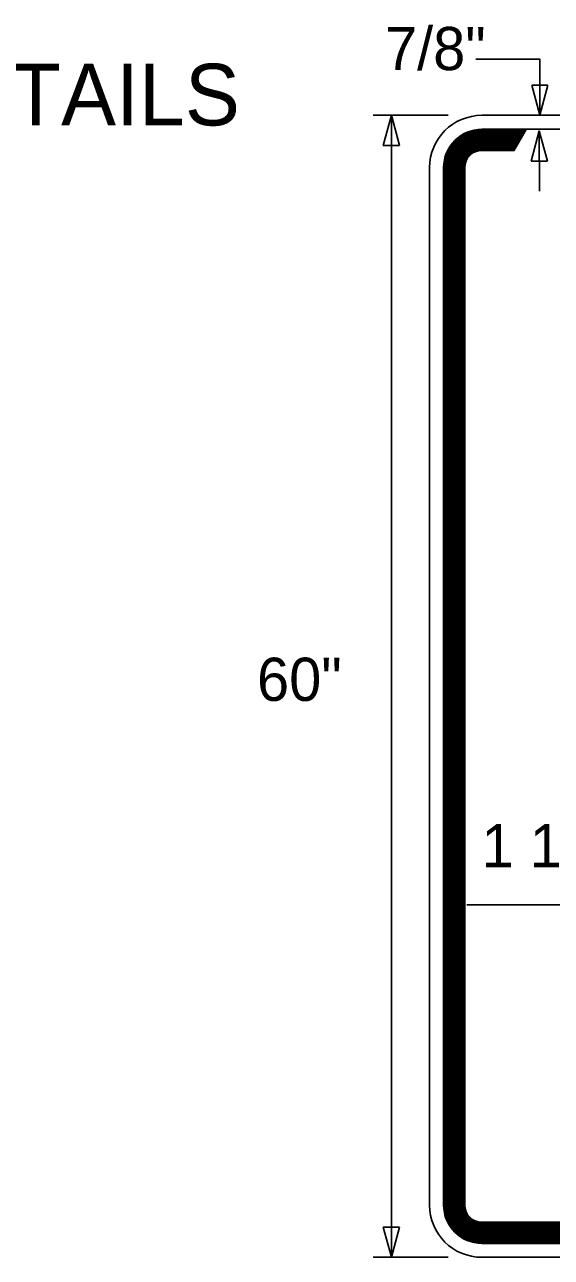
# Model space of a CAD drawing. Extents: x 15278 to 18126, y 1908 to 6555.
# Drawn here: x 17744.9 to 17847.4, y 2366.5 to 2606.5 of the extents above; entities that cross this region are included whole.
import ezdxf

# ---------------------------------------------------------------- set-up
doc = ezdxf.new("R2010")
doc.units = 0
doc.layers.add('TYPICAL_EX', color=7, linetype='Continuous')
doc.layers.add('TYPICAL_TEXT_DIMEN_PR', color=7, linetype='Continuous')

msp = doc.modelspace()

# ---------------------------------------------------------------- linework, layer by layer
at = {"layer": 'TYPICAL_EX'}
for p, q in [((17976.4, 2588.82), (17833.88, 2588.82)), ((17842.58, 2586.1), (17833.89, 2586.1)), ((17842.52, 2585.99), (17833.89, 2585.99)), ((17842.45, 2585.88), (17833.89, 2585.88)), ((17842.39, 2585.77), (17833.89, 2585.77)), ((17842.32, 2585.66), (17833.89, 2585.66)), ((17842.26, 2585.54), (17833.89, 2585.54)), ((17842.19, 2585.43), (17833.89, 2585.43)), ((17842.13, 2585.32), (17833.89, 2585.32)), ((17842.06, 2585.21), (17833.89, 2585.21)), ((17842, 2585.1), (17833.89, 2585.1)), ((17841.94, 2584.98), (17833.89, 2584.98)), ((17841.87, 2584.87), (17833.89, 2584.87)), ((17841.81, 2584.76), (17833.89, 2584.76)), ((17841.74, 2584.65), (17833.89, 2584.65)), ((17841.68, 2584.53), (17833.89, 2584.53)), ((17841.61, 2584.42), (17833.89, 2584.42)), ((17841.55, 2584.31), (17833.89, 2584.31)), ((17841.48, 2584.2), (17833.89, 2584.2)), ((17846.51, 2586.1), (17842.51, 2586.1)), ((17976.4, 2586.1), (17846.51, 2586.1)), ((17841.42, 2584.09), (17833.89, 2584.09)), ((17841.35, 2583.97), (17833.89, 2583.97)), ((17841.29, 2583.86), (17833.89, 2583.86)), ((17841.22, 2583.75), (17833.89, 2583.75)), ((17841.16, 2583.64), (17833.89, 2583.64)), ((17841.1, 2583.53), (17833.89, 2583.53)), ((17841.03, 2583.41), (17833.89, 2583.41)), ((17840.97, 2583.3), (17833.89, 2583.3)), ((17840.9, 2583.19), (17833.89, 2583.19)), ((17840.84, 2583.08), (17833.89, 2583.08)), ((17840.77, 2582.97), (17833.89, 2582.97)), ((17840.71, 2582.85), (17833.89, 2582.85)), ((17840.64, 2582.74), (17833.89, 2582.74)), ((17840.58, 2582.63), (17833.89, 2582.63)), ((17840.51, 2582.52), (17833.89, 2582.52)), ((17840.45, 2582.41), (17833.89, 2582.41)), ((17840.39, 2582.29), (17833.89, 2582.29)), ((17840.32, 2582.18), (17833.89, 2582.18)), ((17840.26, 2582.07), (17833.89, 2582.07)), ((17840.21, 2581.99), (17833.89, 2581.99)), ((17823.7, 2578.64), (17823.7, 2430.55)), ((17826.42, 2578.64), (17826.42, 2430.55)), ((17826.53, 2578.64), (17826.53, 2430.55)), ((17826.64, 2578.64), (17826.64, 2430.55)), ((17826.76, 2578.64), (17826.76, 2430.55)), ((17826.87, 2578.64), (17826.87, 2430.42)), ((17826.98, 2578.64), (17826.98, 2430.55)), ((17827.09, 2578.64), (17827.09, 2430.55)), ((17827.2, 2578.64), (17827.2, 2430.53)), ((17827.32, 2578.64), (17827.32, 2430.56)), ((17827.43, 2578.64), (17827.43, 2430.51)), ((17827.54, 2578.64), (17827.54, 2430.55)), ((17827.65, 2578.64), (17827.65, 2430.55)), ((17827.76, 2578.64), (17827.76, 2430.59)), ((17827.88, 2578.64), (17827.88, 2430.55)), ((17827.99, 2578.64), (17827.99, 2430.55)), ((17828.1, 2578.64), (17828.1, 2430.55)), ((17828.21, 2578.64), (17828.21, 2430.55)), ((17828.33, 2578.64), (17828.33, 2430.55)), ((17828.44, 2578.64), (17828.44, 2430.54)), ((17828.55, 2578.64), (17828.55, 2430.55)), ((17828.66, 2578.64), (17828.66, 2430.56)), ((17828.77, 2578.64), (17828.77, 2430.55)), ((17828.89, 2578.64), (17828.89, 2430.55)), ((17829, 2578.64), (17829, 2430.54)), ((17829.11, 2578.64), (17829.11, 2430.57)), ((17829.22, 2578.64), (17829.22, 2430.55)), ((17829.33, 2578.64), (17829.33, 2430.55)), ((17829.44, 2578.64), (17829.44, 2449.25)), ((17829.56, 2578.64), (17829.56, 2449.25)), ((17829.67, 2578.64), (17829.67, 2449.25)), ((17829.78, 2578.64), (17829.78, 2430.55)), ((17829.89, 2578.64), (17829.89, 2430.54)), ((17830.01, 2578.64), (17830.01, 2430.55)), ((17830.12, 2578.64), (17830.12, 2430.54)), ((17830.23, 2578.64), (17830.23, 2430.55)), ((17830.34, 2578.64), (17830.34, 2430.57)), ((17830.45, 2578.64), (17830.45, 2430.56)), ((17830.53, 2578.64), (17830.53, 2430.57)), ((17829.44, 2449.33), (17829.44, 2376.7)), ((17829.56, 2449.25), (17829.56, 2376.7)), ((17829.67, 2449.25), (17829.67, 2376.7)), ((17830.94, 2435.12), (17979.69, 2435.12)), ((17823.7, 2430.55), (17823.7, 2376.7)), ((17826.42, 2430.55), (17826.42, 2376.7)), ((17826.53, 2430.55), (17826.53, 2376.7)), ((17826.64, 2430.55), (17826.64, 2376.7)), ((17826.76, 2430.55), (17826.76, 2376.7)), ((17826.87, 2430.55), (17826.87, 2376.7)), ((17826.98, 2430.55), (17826.98, 2376.7)), ((17827.09, 2430.55), (17827.09, 2376.7)), ((17827.2, 2430.55), (17827.2, 2376.03)), ((17827.32, 2430.55), (17827.32, 2376.7)), ((17827.43, 2430.55), (17827.43, 2376.7)), ((17827.54, 2430.55), (17827.54, 2376.7)), ((17827.65, 2430.55), (17827.65, 2376.7)), ((17827.76, 2430.6), (17827.76, 2376.7)), ((17827.88, 2430.55), (17827.88, 2376.7)), ((17827.99, 2430.55), (17827.99, 2376.7)), ((17828.1, 2430.55), (17828.1, 2376.7)), ((17828.21, 2430.55), (17828.21, 2376.7)), ((17828.33, 2430.55), (17828.33, 2376.7)), ((17828.44, 2430.55), (17828.44, 2376.7)), ((17828.55, 2430.55), (17828.55, 2376.7)), ((17828.66, 2430.55), (17828.66, 2376.7)), ((17828.77, 2430.55), (17828.77, 2376.7)), ((17828.89, 2430.55), (17828.89, 2376.7)), ((17829, 2430.55), (17829, 2376.7)), ((17829.11, 2430.55), (17829.11, 2376.7)), ((17829.22, 2430.55), (17829.22, 2376.7)), ((17829.33, 2430.55), (17829.33, 2376.7)), ((17829.78, 2430.55), (17829.78, 2376.7)), ((17829.89, 2430.55), (17829.89, 2376.7)), ((17830.01, 2430.55), (17830.01, 2376.7)), ((17830.12, 2430.54), (17830.12, 2376.7)), ((17830.23, 2430.55), (17830.23, 2376.7)), ((17830.34, 2430.55), (17830.34, 2376.7)), ((17830.45, 2430.55), (17830.45, 2376.7)), ((17830.53, 2430.55), (17830.53, 2376.7)), ((17833.88, 2373.35), (17976.4, 2373.35)), ((17833.88, 2373.27), (17976.4, 2373.27)), ((17833.88, 2373.16), (17976.4, 2373.16)), ((17833.88, 2373.05), (17976.4, 2373.05)), ((17833.88, 2372.94), (17976.4, 2372.94)), ((17833.88, 2372.83), (17976.4, 2372.83)), ((17833.88, 2372.71), (17976.4, 2372.71)), ((17833.88, 2372.6), (17976.4, 2372.6)), ((17833.88, 2372.49), (17976.4, 2372.49)), ((17833.88, 2372.38), (17976.4, 2372.38)), ((17833.88, 2372.27), (17976.4, 2372.27)), ((17833.88, 2372.15), (17976.4, 2372.15)), ((17833.88, 2372.04), (17976.4, 2372.04)), ((17833.88, 2371.93), (17976.4, 2371.93)), ((17833.88, 2371.82), (17976.4, 2371.82)), ((17833.88, 2371.7), (17976.4, 2371.7)), ((17833.88, 2371.59), (17976.4, 2371.59)), ((17833.88, 2371.48), (17976.4, 2371.48)), ((17833.88, 2371.37), (17976.4, 2371.37)), ((17833.88, 2371.26), (17976.4, 2371.26)), ((17833.88, 2371.14), (17976.4, 2371.14)), ((17833.88, 2371.03), (17976.4, 2371.03)), ((17833.88, 2370.92), (17976.4, 2370.92)), ((17833.88, 2370.81), (17976.4, 2370.81)), ((17833.88, 2370.7), (17976.4, 2370.7)), ((17833.88, 2370.59), (17976.4, 2370.59)), ((17833.88, 2370.47), (17976.4, 2370.47)), ((17833.88, 2370.36), (17976.4, 2370.36)), ((17833.88, 2370.25), (17976.4, 2370.25)), ((17833.88, 2370.14), (17976.4, 2370.14)), ((17833.88, 2370.02), (17976.4, 2370.02)), ((17833.88, 2369.91), (17976.4, 2369.91)), ((17833.88, 2369.8), (17976.4, 2369.8)), ((17833.88, 2369.69), (17976.4, 2369.69)), ((17833.88, 2369.58), (17976.4, 2369.58)), ((17833.88, 2369.46), (17976.4, 2369.46)), ((17833.88, 2369.35), (17976.4, 2369.35)), ((17833.88, 2369.24), (17976.4, 2369.24)), ((17833.88, 2366.53), (17976.4, 2366.53))]:
    msp.add_line(p, q, dxfattribs=at)
for centre, radius, start, end in [((17833.88, 2578.64), 10.18, 90, 180), ((17833.88, 2578.64), 7.46, 90, 180), ((17833.88, 2578.64), 7.35, 90, 180), ((17833.88, 2578.64), 7.24, 90, 180), ((17833.88, 2578.64), 7.13, 90, 180), ((17833.88, 2578.64), 7.02, 90, 180), ((17833.88, 2578.64), 6.9, 90, 180), ((17833.88, 2578.64), 6.79, 90, 180), ((17833.88, 2578.64), 6.68, 90, 180), ((17833.88, 2578.64), 6.57, 90, 180), ((17833.88, 2578.64), 6.46, 90, 180), ((17833.88, 2578.64), 6.34, 90, 180), ((17833.88, 2578.64), 6.23, 90, 180), ((17833.88, 2578.64), 6.12, 90, 180), ((17833.88, 2578.64), 6.01, 90, 180), ((17833.88, 2578.64), 5.9, 90, 180), ((17833.88, 2578.64), 5.78, 90, 180), ((17833.88, 2578.64), 5.67, 90, 180), ((17833.88, 2578.64), 5.56, 90, 180), ((17833.88, 2578.64), 5.45, 90, 180), ((17833.88, 2578.64), 5.34, 90, 180), ((17833.88, 2578.64), 5.22, 90, 180), ((17833.88, 2578.64), 5.11, 90, 180), ((17833.88, 2578.64), 5, 90, 180), ((17833.88, 2578.64), 4.89, 90, 180), ((17833.88, 2578.64), 4.78, 90, 180), ((17833.88, 2578.64), 4.66, 90, 180), ((17833.88, 2578.64), 4.55, 90, 180), ((17833.88, 2578.64), 4.44, 90, 180), ((17833.88, 2578.64), 4.33, 90, 180), ((17833.88, 2578.64), 4.21, 90, 180), ((17833.88, 2578.64), 4.1, 90, 180), ((17833.88, 2578.64), 3.99, 90, 180), ((17833.88, 2578.64), 3.88, 90, 180), ((17833.88, 2578.64), 3.77, 90, 180), ((17833.88, 2578.64), 3.65, 90, 180), ((17833.88, 2578.64), 3.54, 90, 180), ((17833.88, 2578.64), 3.43, 90, 180), ((17833.88, 2578.64), 3.36, 90, 180), ((17833.88, 2376.71), 10.18, 180, 270), ((17833.88, 2376.71), 7.46, 180, 270), ((17833.88, 2376.71), 7.35, 180, 270), ((17833.88, 2376.71), 7.24, 180, 270), ((17833.88, 2376.71), 7.13, 180, 270), ((17833.88, 2376.71), 7.02, 180, 270), ((17833.88, 2376.71), 6.9, 180, 270), ((17833.88, 2376.71), 6.79, 180, 270), ((17833.88, 2376.71), 6.68, 180, 270), ((17833.88, 2376.71), 6.57, 180, 270), ((17833.88, 2376.71), 6.46, 180, 270), ((17833.88, 2376.71), 6.34, 180, 270), ((17833.88, 2376.71), 6.23, 180, 270), ((17833.88, 2376.71), 6.12, 180, 270), ((17833.88, 2376.71), 6.01, 180, 270), ((17833.88, 2376.71), 5.9, 180, 270), ((17833.88, 2376.71), 5.78, 180, 270), ((17833.88, 2376.71), 5.67, 180, 270), ((17833.88, 2376.71), 5.56, 180, 270), ((17833.88, 2376.71), 5.45, 180, 270), ((17833.88, 2376.71), 5.34, 180, 270), ((17833.88, 2376.71), 5.22, 180, 270), ((17833.88, 2376.71), 5.11, 180, 270), ((17833.88, 2376.71), 5, 180, 270), ((17833.88, 2376.71), 4.89, 180, 270), ((17833.88, 2376.71), 4.78, 180, 270), ((17833.88, 2376.71), 4.66, 180, 270), ((17833.88, 2376.71), 4.55, 180, 270), ((17833.88, 2376.71), 4.44, 180, 270), ((17833.88, 2376.71), 4.33, 180, 270), ((17833.88, 2376.71), 4.21, 180, 270), ((17833.88, 2376.71), 4.1, 180, 270), ((17833.88, 2376.71), 3.99, 180, 270), ((17833.88, 2376.71), 3.88, 180, 270), ((17833.88, 2376.71), 3.77, 180, 270), ((17833.88, 2376.71), 3.65, 180, 270), ((17833.88, 2376.71), 3.54, 180, 270), ((17833.88, 2376.71), 3.43, 180, 270), ((17833.88, 2376.71), 3.36, 180, 270)]:
    msp.add_arc(centre, radius, start, end, dxfattribs=at)
at = {"layer": 'TYPICAL_TEXT_DIMEN_PR'}
for p, q in [((17832.69, 2599.74), (17845.14, 2599.72)), ((17845.14, 2588.82), (17845.13, 2599.82)), ((17845.14, 2588.82), (17843.57, 2594.68)), ((17843.57, 2594.68), (17845.14, 2594.68)), ((17845.14, 2594.68), (17846.71, 2594.68)), ((17846.71, 2594.68), (17845.14, 2588.82)), ((17827.33, 2588.82), (17812.72, 2588.82)), ((17814.69, 2582.96), (17816.26, 2588.82)), ((17816.26, 2430.55), (17816.26, 2588.82)), ((17816.26, 2588.82), (17817.83, 2582.96)), ((17843.48, 2579.91), (17845.03, 2585.77)), ((17845.06, 2574.06), (17845.03, 2585.77)), ((17845.03, 2585.77), (17846.62, 2579.91)), ((17816.26, 2582.96), (17814.69, 2582.96)), ((17817.83, 2582.96), (17816.26, 2582.96)), ((17845.05, 2579.91), (17843.48, 2579.91)), ((17846.62, 2579.91), (17845.05, 2579.91)), ((17816.26, 2366.53), (17816.26, 2430.55)), ((17816.26, 2366.53), (17814.69, 2372.39)), ((17814.69, 2372.39), (17816.26, 2372.39)), ((17816.26, 2372.39), (17817.83, 2372.39)), ((17817.83, 2372.39), (17816.26, 2366.53)), ((17827.33, 2366.53), (17812.72, 2366.53))]:
    msp.add_line(p, q, dxfattribs=at)

# ---------------------------------------------------------------- texts
for s, height, p in [('7/8"', 8.4, (17815.02, 2597.62)), ('SIGN DETAILS', 12, (17676.24, 2586.85)), ('60"', 8.4, (17790.14, 2474.84)), ('1 1/4"', 8.4, (17833.8, 2442.45))]:
    msp.add_text(s, height=height, dxfattribs=at).set_placement(p)

doc.saveas('drawing.dxf')
